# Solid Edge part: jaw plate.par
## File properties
Title: Jaw Plate
Author: Abhinav
Template: Normal.par
Last saved by: Robert a Rhodes jr
Revision: 7
Application: Solid Edge
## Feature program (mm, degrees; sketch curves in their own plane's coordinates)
sketch for "unnamed Protrusion 1" plane through (0, 0, 0) normal (0, -1, 0) x-axis (1, 0, 0)
  line (-34.925, 22.225) -> (34.925, 22.225)
  line (34.925, 22.225) -> (34.925, -22.225)
  line (34.925, -22.225) -> (-34.925, -22.225)
  line (-34.925, -22.225) -> (-34.925, 22.225)
extrude "unnamed Protrusion 1" add finite 4.7498 symmetric
sketch for "unnamed Hole 1" plane through (0, -2.3749, 0) normal (0, -1, 0) x-axis (1, 0, 0)
  hole centre (19.05, 3.175) bore radius 3.175
hole "unnamed Hole 1" through
sketch for "unnamed Hole 2" plane through (0, -2.3749, 0) normal (0, -1, 0) x-axis (1, 0, 0)
  hole centre (-19.05, 3.175) bore radius 3.175
  dimension (linear) = 19.05
  dimension (linear) = 19.05
hole "unnamed Hole 2" through
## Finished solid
Body 1: solid body, 6 faces, 12 edges, 8 vertices.
  Faces by surface: plane 6
  Edges by curve: line 12
Bounding box of the edges (mm): 69.850 x 4.750 x 44.450, from (-34.925, -2.3749, -22.225) to (34.925, 2.3749, 22.225).
Planar faces by outward normal: +x 1, +y 1, +z 1, -x 1, -y 1, -z 1
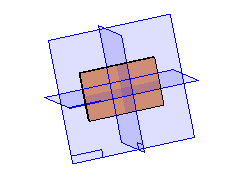
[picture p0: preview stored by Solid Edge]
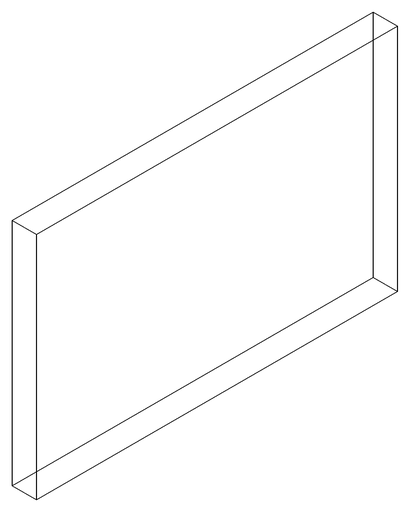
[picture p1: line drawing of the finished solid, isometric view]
